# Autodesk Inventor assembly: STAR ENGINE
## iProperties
Shininess: 64.0
Length Units: 11269
Angle Units: 11279
Time Units: 11290
Mass Units: 11283
Length Display Precision: 3
Angle Display Precision: 2
Compacted: True
Created: 2004-05
Part Number: STAR ENGINE
Document SubType Name: Assembly
Designer: Daniel
Manufacturer: Standard
Standards Organization: Custom
Density: 0.0
Volumn: 0.0
Area: 0.0
PropertySet Name: Model Information
Control State: 0
Master: False
Checked Out: False
Author: Daniel
